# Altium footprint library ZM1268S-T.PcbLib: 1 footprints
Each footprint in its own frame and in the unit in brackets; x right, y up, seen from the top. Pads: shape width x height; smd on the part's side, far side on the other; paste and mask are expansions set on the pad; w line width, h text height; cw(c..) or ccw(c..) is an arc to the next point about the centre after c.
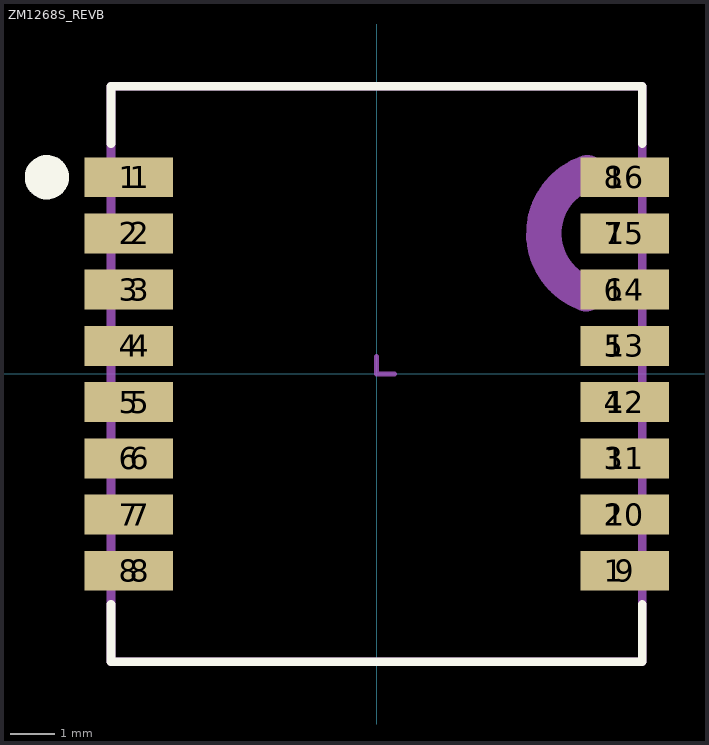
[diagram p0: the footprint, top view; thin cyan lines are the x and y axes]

## ZM1268S_REVB [mm]
pads (32):
  rect 2x0.9 smd: 1(-5.6,4.445) 2(-5.6,3.175) 3(-5.6,1.905) 4(-5.6,0.635) 5(-5.6,-0.635) 6(-5.6,-1.905) 7(-5.6,-3.175) 8(-5.6,-4.445) 9(5.6,-4.445) 10(5.6,-3.175) 11(5.6,-1.905) 12(5.6,-0.635) 13(5.6,0.635) 14(5.6,1.905) 15(5.6,3.175) 16(5.6,4.445)
  rect 1.3x0.9 on Mech15 paste-0.5 mask+0.051: 1(-5.35,4.445) 1(5.35,-4.445) 2(-5.35,3.175) 2(5.35,-3.175) 3(-5.35,1.905) 3(5.35,-1.905) 4(-5.35,0.635) 4(5.35,-0.635) 5(-5.35,-0.635) 5(5.35,0.635) 6(-5.35,-1.905) 6(5.35,1.905) 7(-5.35,-3.175) 7(5.35,3.175) 8(-5.35,-4.445) 8(5.35,4.445)
Top Overlay:
  circle w0.5: c-7.45,4.445 r0.25
  lines w0.2: -6,-5.207 -6,-6.5 6,-6.5 6,-5.207 ; -6,5.207 -6,6.5 6,6.5 6,5.207
Mechanical 15:
  lines w0.114: 0,0.4 0,0 0.4,0
  lines w0.2: -6,-6.5 -6,6.5 6,6.5 6,-6.5 -6,-6.5
  lines w0.8: 4.728,1.813 cw(c5.225,3.175) 4.753,4.546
